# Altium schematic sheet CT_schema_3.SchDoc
size 287 x 163 mm
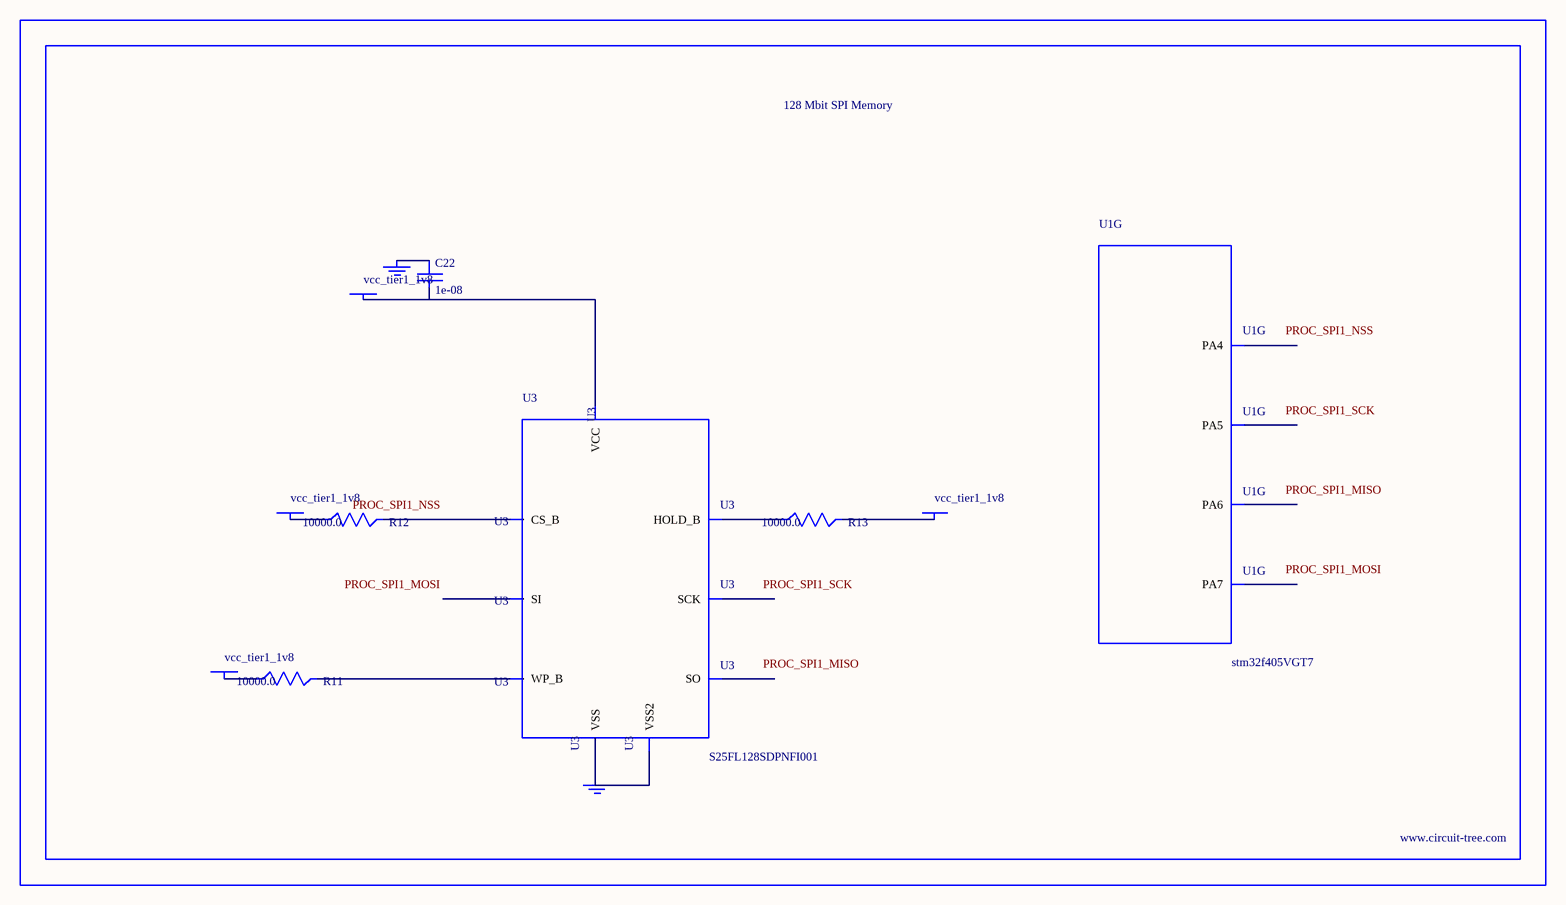
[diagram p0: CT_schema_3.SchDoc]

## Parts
BORDER2  (no value)
C22  1e-08  [C0402]
GND_INSTANCE_2_0  (no value)
GND_INSTANCE_2_1  (no value)
POWER_INSTANCE_2_0  vcc_tier1_1v8
POWER_INSTANCE_2_1  vcc_tier1_1v8
POWER_INSTANCE_2_2  vcc_tier1_1v8
POWER_INSTANCE_2_3  vcc_tier1_1v8
R11  10000.0  [R0603]
R12  10000.0  [R0603]
R13  10000.0  [R0603]
U1  stm32f405VGT7  [LQFP100]  (part G of 10)
U3  S25FL128SDPNFI001  [WNG008]

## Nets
NetC22_1: C22.1 GND_INSTANCE_2_0.0(GND)
NetC22_2: C22.2 POWER_INSTANCE_2_3.0(PWR) U3.8(VCC)
NetGND_INSTANCE_2_1_0: GND_INSTANCE_2_1.0(GND) U3.4(VSS) U3.PAD(VSS2)
NetPOWER_INSTANCE_2_0_0: POWER_INSTANCE_2_0.0(PWR) R12.1
NetPOWER_INSTANCE_2_1_0: POWER_INSTANCE_2_1.0(PWR) R11.1
NetPOWER_INSTANCE_2_2_0: POWER_INSTANCE_2_2.0(PWR) R13.2
NetR11_2: R11.2 U3.3(WP_B)
NetR12_2: R12.2 U3.1(CS_B)
NetR13_1: R13.1 U3.7(HOLD_B)

Not connected (* = marked no-connect by the designer): U1 29(PA4) 30(PA5) 31(PA6) 32(PA7); U3 2(SO) 5(SI) 6(SCK)

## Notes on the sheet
- Labels drawn without touching a wire or pin: PROC_SPI1_MISO, PROC_SPI1_MOSI, PROC_SPI1_NSS, PROC_SPI1_SCK

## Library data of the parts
BORDER2 = BORDER_PAGE2
C22 = C0402C103K3RAC
GND_INSTANCE_2_0 GND_INSTANCE_2_1 = GND
POWER_INSTANCE_2_0-POWER_INSTANCE_2_3 = PWR
R11-R13 = RC0603JR-0710KL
